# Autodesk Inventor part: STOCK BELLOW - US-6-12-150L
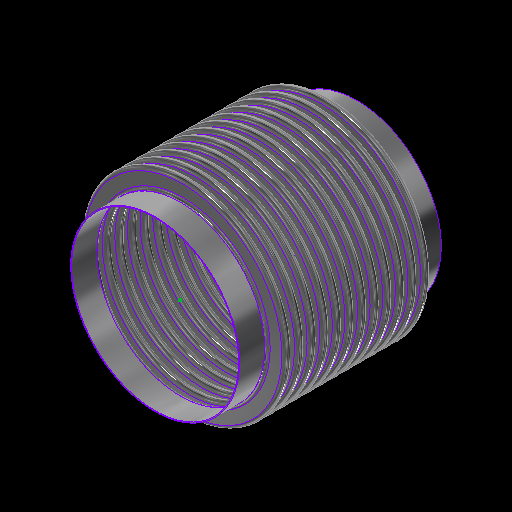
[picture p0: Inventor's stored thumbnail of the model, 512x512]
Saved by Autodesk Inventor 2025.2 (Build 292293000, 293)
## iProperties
Category: 20 GA (0.036 THICK)
RuleStatus: InUse
Created: 2024-01
Part Number: STOCK BELLOW - US-6-12-150L
Project: =STOCK BELLOWS: <Stock Number><SFILL>
Material: ASTM A240-304
Description: =STOCK BELLOWS: <Stock Number>, <SID_> I.D., <SOD_> O.D., <SPLY_> PLY, <Category>, <SNET_CONS> CONS.<PITCH_><STANGENT_> TANGENT<SFILL>
Document SubType Name: Sheet Metal
Designer: GS
Stock Number: U.S-6-12-150L
Surface Area: 6715.99 cm^2
Volume: 305.722 cm^3
Sheet Metal Rule: Default
Appearance: STAINLESS STEEL
Mass: 2463.29 g
Density: 8.05729 g/cm^3
THK: 0.036
ID: 3.500
OD: 4.250
CONS_: 2
PITCH: 0.500
TANGENT: 0.500
BELLOWS_UPSET: 0.000
d79: 1.000
d82: 1.000
d83: 26.000
d84: 24.000
d174: 8
d214: 8
STHK_: 0.036
SID_: 6.625
SOD_: 8.125
SPITCH_: 0.500
STANGENT__: 1.000
SBELLOWS_UPSET_: 0.000
SDIFF_TAN: 1.000
d252: 2
d275: 2
d287: 0.050
d289: 0.500
d290: 0.000
SOD_NECK: 6 11/16
PLY: 1
PSET: 4.178
PBAR: 1.035
COUNTER: 1.500
NET_TUBE: 3.071
CONS: 2
S_CONS: 0
NET_CONS: 2
ID_M: 88.90 mm
OD_M: 107.95 mm
THK_M: 0.91 mm
ID_U: 3.500 in
OD_U: 4.250 in
THK_U: 0.036 in
TANGENT2: 0.500
TAN_TO_TAN: 1.000 in
d80: 2.571
d81: 10
SID: 2.375
SCONS_: 12
SPITCH: 0.250
STANGENT_: 1.000
SBELLOWS_UPSET: 0.000
SNET_CONS: 12
SS_CONS: 0
SCONS: 8
d190: 8
d191: 1
d192: 1
d193: 8
d194: 0
SIZE: 6.00
PRESSURE: 150
d230: 8
STANGENT: 4.000
SPLY_: 1
d233: 8
d234: 0
d263: 2
d265: 1
d268: 2
d269: 0
d286: 2
d288: 1
d291: 2
d292: 0
SREROLL: 0.750
BLETP: 1.000 ul
PRES_Copy: 85
MATTABLE: 20 GA (0.036 THICK)
PART_NUMBER: U.S-6-12-150L
PITCH_: =, <SPITCH_> PITCH,
CFILL: .
SFILL: .
MESH: ,
COMP: 1.25
EXT: 0.63
LAT: 0.34
ANG: 573
ASR: 1215
LSR: 2478
ANSR: 130
PRES: 150
COMPM: 12.5
EXTM: 6.25
LATM: 3.40
ASRM: 212.783
PRESM: 10.342
LSRM: 433.972
ANSRM: 22.767
TEMPMIN: 20
TEMPMAX: 800
TEMPMINM: -7
TEMPMAXM: 427
WEIGHTM: 2.463
WEIGHT: 5.431
Author: GS
Keywords: 20 GA (0.036 THICK)
Comments: =STOCK BELLOW - <STOCK NUMBER>
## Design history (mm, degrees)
sketch "Sketch2"
  geometry: L1 (0, -177.245)-(0, 562.856) reference; L2 (45.364, 0)-(44.45, 0); L3 (48.082, -2.718)-(50.343, -2.718); L4 (48.082, -3.632)-(50.343, -3.632); L5 (50.343, -9.982)-(48.082, -9.982); L6 (50.343, -9.068)-(48.082, -9.068); L7 (45.364, -12.7)-(44.45, -12.7); L8 (48.082, 0)-(48.082, -12.7); L9 (50.343, -6.35)-(53.975, -6.35); L10 (44.45, 0)-(44.45, -12.7); L11 (20.376, 102.841)-(20.376, 101.926); L12 (58.262, 457.127)-(58.262, 349.177); L13 (58.262, 444.427)-(58.262, 336.477); L14 (93.133, -58.817)-(93.133, -71.517); L15 (118.746, -66.401)-(118.746, -66.401); L16 (50.343, -9.068)-(50.343, -9.982); L17 (48.082, -9.068)-(48.082, -9.982); L18 (48.082, -9.525)-(50.343, -9.525); L19 (53.975, 0)-(53.975, -12.7); L20 (-50.343, -9.068)-(-50.343, -9.982); L21 (-50.343, -2.718)-(-48.082, -2.718); L22 (-50.343, -3.632)-(-48.082, -3.632); L23 (-48.082, -9.068)-(-50.343, -9.068); L24 (-50.343, -9.525)-(-48.082, -9.525); L25 (-48.082, -9.982)-(-50.343, -9.982); L26 (-48.082, -9.068)-(-48.082, -9.982); L27 (-44.45, 0.653)-(-44.45, -12.047); L28 (-48.082, -6.35)-(-44.45, -6.35); L29 (-50.343, 0.653)-(-50.343, -12.7); L30 (-53.061, 0)-(-53.975, 0); L31 (-53.975, 0)-(-53.975, -12.7); L32 (-53.061, -12.7)-(-53.975, -12.7); A1 r 2.718 centre (48.082, 0) between (45.364, 0) and (48.082, -2.718); A2 r 3.632 centre (48.082, 0) between (44.45, 0) and (48.082, -3.632); A3 r 3.632 centre (50.343, -6.35) between (50.343, -9.982) and (50.343, -2.718); A4 r 2.718 centre (50.343, -6.35) between (50.343, -9.068) and (50.343, -3.632); A5 r 2.718 centre (48.082, -12.7) between (48.082, -9.982) and (45.364, -12.7); A6 r 3.632 centre (48.082, -12.7) between (48.082, -9.068) and (44.45, -12.7); A7 r 3.175 centre (50.343, -6.35) between (50.343, -9.525) and (53.518, -6.35); A8 r 3.175 centre (48.082, -12.7) between (48.082, -9.525) and (44.907, -12.7); A9 r 2.718 centre (-50.343, -12.7) between (-50.343, -9.982) and (-53.061, -12.7); A10 r 2.718 centre (-48.082, -6.35) between (-48.082, -9.068) and (-48.082, -3.632); A11 r 3.175 centre (-48.082, -6.35) between (-48.082, -9.525) and (-44.907, -6.35); A12 r 3.632 centre (-48.082, -6.35) between (-48.082, -9.982) and (-48.082, -2.718); A13 r 3.175 centre (-50.343, -12.7) between (-50.343, -9.525) and (-53.518, -12.7); A14 r 3.632 centre (-50.343, -12.7) between (-50.343, -9.068) and (-53.975, -12.7); A15 r 2.718 centre (-50.343, 0) between (-53.061, 0) and (-50.343, -2.718); A16 r 3.632 centre (-50.343, 0) between (-53.975, 0) and (-50.343, -3.632); 10 further points
  constraints: 62 end point, 38 point on circle, 20 tangent, 16 centre point, 12 parallel, 9 midpoint, 7 vertical, 6 coincident, 6 concentric, 6 point on line, 4 equal radius, 4 perpendicular, 3 horizontal, 1 collinear, 1 horizontal alignment, 10 other
  dimensions: "THK" = 0.9144 distance of L11.start L11.end; "ID" = 88.9 distance of L11.end point (20.376, 13.026); "OD" = 107.95 distance of L12.start L12.end; "PITCH" = 12.7 distance of L12.start L13.start; "TANGENT" = 12.7 distance of L14.start L14.end; "BELLOWS_UPSET" = 0 distance of L15.start L15.end; "d43" = 88.9 diameter of L10 L1 (= ID); "d44" = 107.95 diameter of L9.end L1 (= OD); "d45" = 0.9144 distance between parallel lines of L5 L6 (computed from THK, PLY); "d46" = 3.6322 radius of A3 (computed from PITCH, THK, PLY); "UPSET_PITCH" = 12.7 distance of L2.end L7.end (derived); "SIDEWALL_ANGLE" = 360 deg dimension on L3 L9 (derived); "CON_GAP" = 5.4356 distance of point (48.082, -9.068) point (48.082, -3.632) (derived); "TAN1" = 4.98728 dimension on A8 (derived); "TAN2" = 4.98728 dimension on A7 (derived); "LEG1" = 2.2606 distance of L18.start L18.end (derived); "d278" = 0.9144 distance between parallel lines of L25 L23 (derived); "d279" = 3.6322 radius of A12 (derived); "d280" = 12.7 distance of L30.end L31.end (derived); "d281" = 360 deg dimension on L21 L28 (derived); "d282" = 5.4356 distance of point (-50.343, -9.068) point (-50.343, -3.632) (derived); "d283" = 4.98728 dimension on A13 (derived); "d284" = 4.98728 dimension on A11 (derived); "d285" = 2.2606 distance of L24.start L24.end (derived); "d293" = 88.9 diameter of L27 L1 (derived); "d294" = 107.95 diameter of L31 L1 (derived)
  node "Sketch Rectangular Pattern1" dims "d31" = 25.4, "ID" = 88.9
  node "Sketch Rectangular Pattern2" dims "d39" = 25.4, "PITCH" = 12.7
revolve "CONS" stored, may be unused: angle "d48" = 90 deg
node "BELLOW MIDPLANE"
pattern_linear "Rectangular Pattern2" dims "d52" = 12.7 (= UPSET_PITCH)
sketch "Sketch5"
  geometry: C1 r 45.364 at (0, 0) reference; C2 r 44.45 at (0, 0) reference
extrude "TANGENT" new body sketch "Sketch5" distance "d53" = 12.7 (= TANGENT); taper "d54" = 0 deg
revolve "SAMETAN" stored, may be unused: angle "d65" = 90 deg
revolve "DIFFTAN" stored, may be unused: angle "d70" = 90 deg
sketch "Sketch9"
  geometry: L1 (53.319, 0)-(-53.319, 0) reference; L2 (0, -17.78)-(0, 17.78) reference; L3 (38.085, 0)-(-38.085, 0); L4 (38.085, -11.906)-(38.085, 11.906); L5 (25.385, -11.906)-(25.385, 11.906); L6 (13.15, 11.906)-(13.15, -11.906); L7 (-25.385, -11.906)-(-25.385, 11.906); L8 (-38.085, -11.906)-(-38.085, 11.906); L9 (37.291, -11.906)-(37.291, 11.906); L10 (38.085, -11.906)-(37.291, -11.906); L11 (38.085, 11.906)-(37.291, 11.906); L12 (13.546, 11.906)-(12.753, 11.906); L13 (12.753, 11.906)-(12.753, -11.906); L14 (12.753, -11.906)-(13.546, -11.906); L15 (13.546, -11.906)-(13.546, 11.906); L16 (-13.546, 11.906)-(-13.546, -11.906); L17 (-13.15, 11.906)-(-13.15, -11.906); L18 (-13.546, -11.906)-(-12.753, -11.906); L19 (-12.753, -11.906)-(-12.753, 11.906); L20 (-12.753, 11.906)-(-13.546, 11.906); L21 (-38.085, -11.906)-(-37.291, -11.906); L22 (-37.291, -11.906)-(-37.291, 11.906); L23 (-37.291, 11.906)-(-38.085, 11.906); L24 (-38.085, 11.906)-(-38.085, -11.906); L25 (38.085, -0.397)-(-38.085, -0.397); L26 (-38.085, -0.397)-(-38.085, 0.397); L27 (-38.085, 0.397)-(38.085, 0.397); L28 (38.085, 0.397)-(38.085, -0.397); L29 (-38.085, 11.906)-(38.085, 11.906); L30 (38.085, 11.906)-(38.085, 12.7); L31 (38.085, 12.7)-(-38.085, 12.7); L32 (-38.085, 12.7)-(-38.085, 11.906); L33 (38.085, -11.906)-(-38.085, -11.906); L34 (-38.085, -11.906)-(-38.085, -12.7); L35 (-38.085, -12.7)-(38.085, -12.7); L36 (38.085, -12.7)-(38.085, -11.906); 30 further points
  constraints: 68 end point, 13 midpoint, 13 parallel, 8 horizontal, 7 perpendicular, 6 equal length, 3 point on line, 2 vertical, 14 other
  dimensions: "d115" = 23.8125 distance of L4.start L4.end (derived); "d116" = 12.7 distance between parallel lines of L4 L5 (derived); "d117" = 12.23516 distance between parallel lines of L5 L6 (derived); "d125" = 38.53427 distance between parallel lines of L7 L6 (derived); "d127" = 12.7 distance between parallel lines of L8 L7 (derived); "d128" = 24.93516 distance between parallel lines of L6 L4 (derived); "d130" = 76.16943 distance between parallel lines of L8 L4 (derived); "RULER_THK" = 0.79375 distance between parallel lines of L4 L9; "d135" = 0.79375 distance of L13.end L14.end (derived); "d138" = 26.29911 distance of L13.end L16.end (derived); "d143" = 0.79375 distance of L22.end L8.end (derived); "d144" = 0.79375 distance between parallel lines of L27 L25 (derived)
extrude "RULER" join sketch "Sketch9" distance "d149" = 0.79375 (derived); taper "d150" = 0 deg
extrude "BARS" join sketch "Sketch9" distance "d151" = 0.79375 (derived); taper "d152" = 0 deg
pattern_linear "Rectangular Pattern4" dims "d155" = 26.29911 (derived)
sketch "Sketch13"
  geometry: L1 (93.149, -52.467)-(93.149, -77.867); L2 (85.052, 0)-(84.138, 0); L3 (85.052, -12.7)-(84.138, -12.7); L4 (99.555, -9.982)-(87.77, -9.982); L5 (99.555, -9.068)-(87.77, -9.068); L6 (99.555, -6.35)-(103.188, -6.35); L7 (87.77, -2.718)-(99.555, -2.718); L8 (87.77, 0)-(87.77, -12.7); L9 (84.138, 0)-(84.138, -12.7); L10 (58.254, -290.056)-(58.254, -496.431); L11 (58.254, -302.756)-(58.254, -509.131); L12 (58.254, -328.156)-(58.254, -534.531); L13 (58.254, -340.856)-(58.254, -547.231); L14 (58.254, -353.556)-(58.254, -559.931); L15 (58.254, -366.256)-(58.254, -572.631); L16 (58.254, -378.956)-(58.254, -585.331); L17 (58.254, -315.456)-(58.254, -521.831); L18 (20.376, 102.841)-(20.376, 101.926); L19 (87.77, -3.632)-(99.555, -3.632); L20 (0, -722.965)-(0, 240.475) reference; L21 (-23.752, 0)-(142.514, 0) reference; A1 r 2.718 centre (87.77, 0) between (85.052, 0) and (87.77, -2.718); A2 r 2.718 centre (87.77, -12.7) between (87.77, -9.982) and (85.052, -12.7); A3 r 3.632 centre (87.77, -12.7) between (87.77, -9.068) and (84.138, -12.7); A4 r 2.718 centre (99.555, -6.35) between (99.555, -9.068) and (99.555, -3.632); A5 r 3.632 centre (99.555, -6.35) between (99.555, -9.982) and (99.555, -2.718); A6 r 3.632 centre (87.77, 0) between (84.138, 0) and (87.77, -3.632); 6 further points; 1 other entity
  constraints: 38 end point, 15 point on circle, 9 tangent, 6 centre point, 6 parallel, 5 vertical alignment, 4 point on line, 4 vertical, 3 coincident, 3 concentric, 2 collinear, 2 equal radius, 1 horizontal, 1 perpendicular, 23 other
  dimensions: "SBELLOWS_UPSET_" = 0 distance of point (118.762, -66.401) point (118.762, -66.401); "STOTAL_THK_BELLOW__" = 0.9144 distance between parallel lines of L4 L5 (derived); "d224" = 3.6322 radius of A5 (derived); "d225" = 12.7 distance of L2.end L3.end (derived); "SSIDEWALL_ANGLE_" = 0 deg angle of L7 L6 (derived); "SSCON_GAP_" = 5.4356 distance of point (87.77, -9.068) point (87.77, -3.632) (derived); "d235" = 168.275 diameter of L9 L20 (derived); "d236" = 206.375 diameter of L6.end L20 (derived)
  node "Sketch Rectangular Pattern4" dims "d228" = 25.4
  node "Sketch Rectangular Pattern5" dims "d229" = 25.4
revolve "SBELLOW" stored, may be unused: angle "d197" = 90 deg
pattern_linear "Rectangular Pattern5" dims "d204" = 12.7 (derived)
revolve "STANGENT" stored, may be unused: angle "d240" = 90 deg
revolve "SSAMETAN" stored, may be unused: angle "d241" = 90 deg
revolve "SDIFFTAN" stored, may be unused: angle "d246" = 90 deg
revolve "INVCON" stored, may be unused: angle "d295" = 90 deg
pattern_linear "Rectangular Pattern6" dims "d298" = 12.7 (derived)
revolve "INVTANGENT" stored, may be unused: angle "d302" = 90 deg
revolve "INVSAMETAN" stored, may be unused: angle "d307" = 90 deg
revolve "INVDIFFTAN" stored, may be unused: angle "d312" = 90 deg
sketch "ID BELLOW MOUNT CALC"
  geometry: L1 (44.45, 0)-(38.1, 0); L2 (38.1, 0)-(38.1, 12.7); L3 (38.1, 12.7)-(44.45, 12.7); L4 (44.45, 12.7)-(44.45, 0); L5 (36.513, 12.7)-(35.598, 12.7); L6 (35.598, 12.7)-(35.598, 0); L7 (35.598, 0)-(36.513, 0); L8 (36.513, 0)-(36.513, 12.7); L9 (0, -2.54)-(0, 15.24) reference; L10 (-8.89, 0)-(53.34, 0) reference; 1 further point
  constraints: 16 end point, 5 parallel, 2 collinear, 2 horizontal, 2 perpendicular
  dimensions: "d314" = 12.7 distance of L5.end L6.end (derived); "d315" = 0.9144 distance of L5.start L5.end (derived); "IG" = 1.5875 distance between parallel lines of L2 L8; "PIPE_OD" = 88.9 diameter of L4 L9; "PIPE_WALL" = 6.35 distance of L2.end L3.end; "ID_MT_BELLOW" = 71.1962 diameter of L6 L9 (derived)
revolve "CFILL" stored, may be unused: angle "d320" = 90 deg
pattern_linear "Rectangular Pattern7" dims "d323" = 12.7 (derived)
revolve "SFILL" stored, may be unused: angle "d324" = 90 deg
pattern_linear "Rectangular Pattern8" dims "d327" = 12.7 (derived)
node "STOCK BELLOW MIDPLANE"
node "BELLOW"
sketch "Sketch6"
  geometry: L1 (-12.7, 45.364)-(0, 45.364); L2 (0, 45.364)-(0, 44.45); L3 (0, 44.45)-(-12.7, 44.45); L4 (-12.7, 44.45)-(-12.7, 45.364); L5 (10.16, 0)-(-60.96, 0) reference; L6 (-38.1, -89.422)-(-38.1, 153.44) reference; 1 further point
  constraints: 8 end point, 2 parallel, 1 horizontal, 1 perpendicular
  dimensions: "d61" = 12.7 distance of L2.end L3.end (derived); "d62" = 0.9144 distance of L1.end L2.end (derived); "d63" = 88.9 diameter of L3 L5 (derived); "d64" = 25.4 distance between parallel lines of L4 L6 (derived)
sketch "Sketch12"
  geometry: 1 further point
sketch "Sketch14"
  geometry: L1 (-25.4, 85.052)-(0, 85.052); L2 (0, 85.052)-(0, 84.138); L3 (0, 84.138)-(-25.4, 84.138); L4 (-25.4, 84.138)-(-25.4, 85.052); L5 (5.08, 0)-(-30.48, 0) reference; L6 (0, -17.01)-(0, 102.062) reference; 1 further point
  constraints: 8 end point, 2 parallel, 1 collinear, 1 horizontal, 1 perpendicular
  dimensions: "d237" = 0.9144 distance of L3.end L1.start (derived); "d238" = 168.275 diameter of L3 L5 (derived); "d239" = 25.4 distance of L1.start L1.end (derived); "SOD_NECK" = 170.1038 diameter of L1 L5 (derived)
sketch "Sketch15"
  geometry: L1 (-17.01, 0)-(102.062, 0) reference; L2 (84.138, -152.4)-(85.052, -152.4); L3 (85.052, -152.4)-(85.052, -177.8); L4 (85.052, -177.8)-(84.138, -177.8); L5 (84.138, -177.8)-(84.138, -152.4); L6 (0, -215.9)-(0, 50.8) reference; 1 further point
  constraints: 8 end point, 2 parallel, 1 horizontal, 1 perpendicular
  dimensions: "d205" = 25.4 distance of L4.end L2.start (derived); "d206" = 0.9144 distance of L3.end L4.end (derived); "d207" = 168.275 diameter of L5 L6 (derived); "d208" = 152.4 distance between parallel lines of L1 L2 (derived)
node "TANGENT_"
node "SAME_TAN"
sketch "Sketch8"
  geometry: L1 (45.364, -25.4)-(44.45, -25.4); L2 (44.45, -25.4)-(44.45, -38.1); L3 (44.45, -38.1)-(45.364, -38.1); L4 (45.364, -38.1)-(45.364, -25.4); L5 (0, -48.26)-(0, 22.86) reference; L6 (-89.422, 0)-(153.44, 0) reference; 1 further point
  constraints: 8 end point, 2 parallel, 1 horizontal, 1 perpendicular
  dimensions: "d66" = 88.9 diameter of L2 L5 (derived); "TOTAL_THK_BELLOW" = 0.9144 distance of L2.end L3.end (derived); "d68" = 25.4 distance between parallel lines of L1 L6 (derived); "d69" = 12.7 distance of L1.end L2.end (derived)
node "DIFF_TAN"
node "Sketch Rectangular Pattern3" dims "d138" = 26.29911 (derived), "d141" = 25.4
node "SBELLOW_"
node "STANGENT_"
node "SSAME_TAN"
sketch "Sketch16"
  geometry: L1 (85.052, -152.4)-(84.138, -152.4); L2 (84.138, -152.4)-(84.138, -177.8); L3 (84.138, -177.8)-(85.052, -177.8); L4 (85.052, -177.8)-(85.052, -152.4); L5 (0, -215.9)-(0, 50.8) reference; L6 (-17.01, 0)-(102.062, 0) reference; 1 further point
  constraints: 8 end point, 2 parallel, 1 horizontal, 1 perpendicular
  dimensions: "SDIFF_TAN" = 25.4 distance of L3.end L1.start; "d243" = 0.9144 distance of L2.end L3.end (derived); "d244" = 152.4 distance between parallel lines of L1 L6 (derived); "d245" = 168.275 diameter of L2 L5 (derived)
node "SDIFF_TAN"
body "Solid15"
sketch "Sketch17"
  geometry: L1 (53.975, 12.7)-(53.061, 12.7); L2 (53.061, 12.7)-(53.061, 0); L3 (53.061, 0)-(53.975, 0); L4 (53.975, 0)-(53.975, 12.7); L5 (0, -2.54)-(0, 15.24) reference; L6 (-10.795, 0)-(64.77, 0) reference; 2 further points
  constraints: 8 end point, 2 parallel, 1 horizontal, 1 midpoint, 1 perpendicular, 1 point on line
  dimensions: "INVTANGENT" = 12.7 distance of L3.end L1.start (derived); "d300" = 0.9144 distance of L1.start L1.end (derived); "d301" = 107.95 diameter of L4 L5 (derived)
body "Solid16"
sketch "Sketch18"
  geometry: L1 (53.975, -25.4)-(53.061, -25.4); L2 (53.061, -25.4)-(53.061, -38.1); L3 (53.061, -38.1)-(53.975, -38.1); L4 (53.975, -38.1)-(53.975, -25.4); L5 (-10.795, 0)-(64.77, 0) reference; L6 (0, -48.26)-(0, 22.86) reference; 1 further point
  constraints: 8 end point, 2 parallel, 1 horizontal, 1 perpendicular
  dimensions: "d303" = 25.4 distance between parallel lines of L1 L5 (derived); "d304" = 12.7 distance of L3.end L1.start (derived); "d305" = 0.9144 distance of L2.end L3.end (derived); "d306" = 107.95 diameter of L4 L6 (derived)
body "Solid17"
sketch "Sketch19"
  geometry: L1 (53.975, -25.4)-(53.061, -25.4); L2 (53.061, -25.4)-(53.061, -38.1); L3 (53.061, -38.1)-(53.975, -38.1); L4 (53.975, -38.1)-(53.975, -25.4); L5 (0, -48.26)-(0, 22.86) reference; L6 (-10.795, 0)-(64.77, 0) reference; 1 further point
  constraints: 8 end point, 2 parallel, 1 horizontal, 1 perpendicular
  dimensions: "d308" = 12.7 distance of L1.end L2.end (derived); "d309" = 107.95 diameter of L4 L5 (derived); "d310" = 0.9144 distance of L2.end L3.end (derived); "d311" = 25.4 distance between parallel lines of L1 L6 (derived)
body "Solid18"
body "Solid19"
body "Solid20"
other parameters: "BMPL" = -76.2, "PSET" = 106.1212 (computed from OD, THK, PLY) [user parameter], "PBAR" = 26.29911 (= 0.570796 x PITCH + OD - ID) [user parameter; used in 1 equation term], "COUNTER" = 15 [user parameter], "NET_TUBE" = 77.99823 (computed from CONS_, PBAR, TANGENT) [user parameter], "S_CONS" = 0 [user parameter; used in 1 equation term], "ID_M" = 88.9 (= ID) [user parameter], "OD_M" = 107.95 (= OD) [user parameter], "THK_M" = 0.9144 (= THK) [user parameter], "ID_U" = 88.9 (= ID) [user parameter], "OD_U" = 107.95 (= OD) [user parameter], "THK_U" = 0.9144 (= THK) [user parameter], "D_UNITS" = 0 [user parameter], "TANGENT2" = 12.7 [user parameter], "TAN_TO_TAN" = 25.4 [user parameter], "OD_NECK" = 90.7288 [user parameter], "d79" = 25.4, "d80" = 65.29823 [user parameter], "d82" = 25.4, "d83" = 660.4, "d84" = 609.6, "sa_0" = 4, "FRAME_THK" = 0.79375 [user parameter], "CON_FLAT" = 12.23516 [user parameter], "SID" = 60.325 [user parameter], "SPITCH" = 6.35 [user parameter], "STANGENT_" = 25.4 [user parameter], "SBELLOWS_UPSET" = 0 [user parameter], "SS_CONS" = 0 [user parameter], "STAN_TO_TAN_" = 152.4 [user parameter], "d100" = 0.9144 [user parameter], "d191" = 25.4 [user parameter], "d194" = 0 [user parameter], "STANGENT" = 101.6 [user parameter], "d234" = 0 [user parameter], "SUPSET_PITCH_" = 12.7 [user parameter], "d269" = 0 [user parameter], "d287" = 1.27, "d289" = 12.7, "d290" = 0, "d292" = 0 [user parameter], "Thickness" = 3.048 (derived), "KFactor" = 4.4, "BendRadius" = 3.048 (derived), "BendReliefWidth" = 3.048 (derived), "BendReliefDepth" = 1.524 (derived), "CornerReliefSize" = 12.192 (derived), "SeamGap" = 0.00508, "MinimumRemnant" = 6.096 (derived), "TransitionRadius" = 3.048 (derived), "JacobiRadiusSize" = 3.048 (derived), "GapSize" = 3.048 (derived), "SREROLL" = 19.05 [user parameter], "CUR_STK_PITCH" = 12.7 [user parameter], "d328" = -76.2 (derived), "ASR" = 12150 [user parameter], "LSR" = 24780 [user parameter], "BLETP" = 1 [user parameter], "ASRM" = 2127.8295 [user parameter], "PRESM" = 103.41975 [user parameter], "LSRM" = 4339.7214 [user parameter], "ANSRM" = 227.669 [user parameter], "TEMPMIN" = 2664.83333 [user parameter], "TEMPMAX" = 6998.16667 [user parameter], "TEMPMINM" = 2664.83333 [user parameter], "TEMPMAXM" = 6998.16667 [user parameter], "WEIGHT" = 24.63287 [user parameter], "WEIGHTM" = 0.02463 [user parameter]
